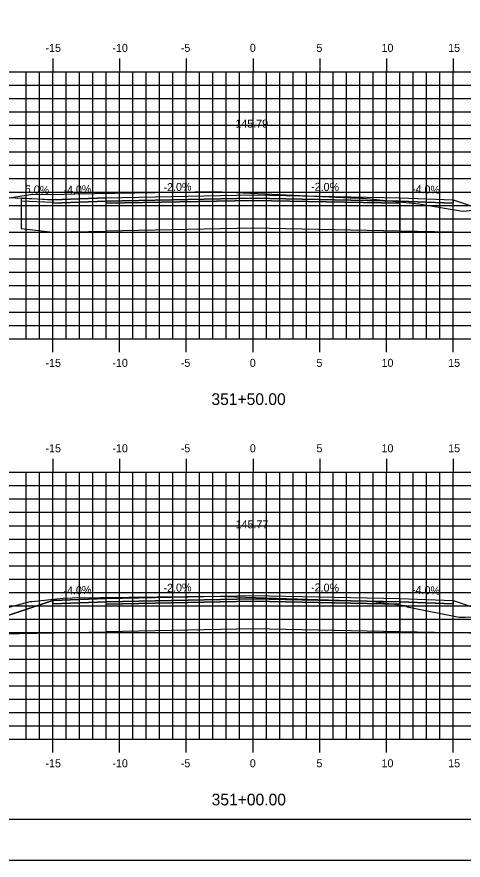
# Model space of a CAD drawing. Extents: x 1144751 to 1144921, y 608981 to 609091.
# Drawn here: x 1144815.9 to 1144849.4, y 608981.3 to 609044.5 of the extents above; entities that cross this region are included whole.
import ezdxf

# ---------------------------------------------------------------- set-up
doc = ezdxf.new("R2010")
doc.units = 0
for name, color, linetype in [('ANNOTATION', 7, 'Continuous'), ('BORDER', 7, 'Continuous'), ('D_Roadway_Centerline', 7, 'Continuous'), ('D_Roadway_Centerline_Text', 7, 'Continuous'), ('D_Roadway_Edge_Shoulder', 7, 'Continuous'), ('D_Roadway_Edge_TW', 7, 'Continuous'), ('D_Roadway_Pavement', 7, 'Continuous'), ('D_Roadway_SlopeLines', 7, 'Continuous'), ('D_Roadway_SubGrade', 7, 'Continuous'), ('H_V ANNOTATION', 7, 'Continuous'), ('MAJOR', 7, 'Continuous'), ('MINOR', 7, 'Continuous'), ('PLOT BOUNDARY', 7, 'Continuous'), ('S_Roadway_Centerline', 7, 'Continuous')]:
    doc.layers.add(name, color=color, linetype=linetype)

msp = doc.modelspace()

# ---------------------------------------------------------------- linework, layer by layer
for points in [[(1144816.245, 609030.888), (1144818.619, 609030.746), (1144822.619, 609030.906), (1144833.619, 609031.126), (1144844.619, 609030.906), (1144848.619, 609030.746), (1144856.342, 609028.171), (1144859.342, 609027.171), (1144862.514, 609028.757), (1144863.764, 609029.299), (1144865.014, 609029.675), (1144866.264, 609029.885), (1144867.514, 609029.928)], [(1144797.455, 609001.234), (1144798.705, 609001.105), (1144799.955, 609000.834), (1144801.205, 609000.422), (1144802.455, 608999.868), (1144807.894, 608997.148), (1144810.894, 608998.148), (1144818.618, 609000.723), (1144818.619, 609000.723), (1144822.619, 609000.883), (1144833.619, 609001.103), (1144844.619, 609000.883), (1144848.619, 609000.723), (1144856.342, 608998.148), (1144859.342, 608997.148), (1144861.625, 608998.29), (1144862.875, 608998.836), (1144864.125, 608999.226), (1144865.375, 608999.458), (1144866.625, 608999.533)]]:
    msp.add_lwpolyline(points)
at = {"layer": 'BORDER'}
msp.add_lwpolyline([(1144758.619, 608984.335), (1144918.619, 608984.335), (1144918.619, 609089.335), (1144758.619, 609089.335)], close=True, dxfattribs=at)
at = {"layer": 'D_Roadway_Edge_Shoulder'}
for points in [[(1144822.619, 609030.906), (1144818.619, 609030.746), (1144818.619, 609030.496), (1144822.619, 609030.656)], [(1144844.619, 609030.906), (1144848.619, 609030.746), (1144848.619, 609030.496), (1144844.619, 609030.656)], [(1144822.619, 609000.883), (1144818.619, 609000.723), (1144818.619, 609000.473), (1144822.619, 609000.633)], [(1144844.619, 609000.883), (1144848.619, 609000.723), (1144848.619, 609000.473), (1144844.619, 609000.633)]]:
    msp.add_lwpolyline(points, close=True, dxfattribs=at)
msp.add_lwpolyline([(1144816.245, 609030.674), (1144818.617, 609030.579), (1144818.619, 609030.746), (1144816.245, 609030.841)], dxfattribs=at)
at = {"layer": 'D_Roadway_Edge_TW'}
for points in [[(1144822.619, 609030.656), (1144822.619, 609030.906), (1144833.619, 609031.126), (1144844.619, 609030.906), (1144844.619, 609030.656), (1144833.619, 609030.876)], [(1144822.619, 609000.633), (1144822.619, 609000.883), (1144833.619, 609001.103), (1144844.619, 609000.883), (1144844.619, 609000.633), (1144833.619, 609000.853)]]:
    msp.add_lwpolyline(points, close=True, dxfattribs=at)
at = {"layer": 'D_Roadway_Pavement'}
for points in [[(1144822.619, 609030.489), (1144822.619, 609030.656), (1144833.619, 609030.876), (1144844.619, 609030.656), (1144844.619, 609030.489), (1144833.619, 609030.709)], [(1144822.619, 609000.466), (1144822.619, 609000.633), (1144833.619, 609000.853), (1144844.619, 609000.633), (1144844.619, 609000.466), (1144833.619, 609000.686)]]:
    msp.add_lwpolyline(points, close=True, dxfattribs=at)
at = {"layer": 'D_Roadway_SlopeLines'}
msp.add_line((1144816.245, 609030.841), (1144798.576, 609031.83), dxfattribs=at)
at = {"layer": 'D_Roadway_SubGrade'}
for points in [[(1144818.619, 609028.326), (1144822.619, 609028.406), (1144822.619, 609030.656), (1144818.619, 609030.496), (1144818.619, 609030.746), (1144816.245, 609030.841), (1144816.245, 609028.6)], [(1144822.619, 609028.406), (1144822.619, 609030.489), (1144833.619, 609030.709), (1144844.619, 609030.489), (1144844.619, 609028.406), (1144833.619, 609028.626)], [(1144844.619, 609030.489), (1144844.619, 609030.656), (1144848.619, 609030.496), (1144848.619, 609030.746), (1144848.619, 609030.746), (1144856.342, 609028.171), (1144844.619, 609028.406)], [(1144822.619, 609000.466), (1144822.619, 609000.633), (1144818.619, 609000.473), (1144818.619, 609000.723), (1144818.618, 609000.723), (1144810.894, 608998.148), (1144822.619, 608998.383)], [(1144822.619, 608998.383), (1144822.619, 609000.466), (1144833.619, 609000.686), (1144844.619, 609000.466), (1144844.619, 608998.383), (1144833.619, 608998.603)], [(1144844.619, 609000.466), (1144844.619, 609000.633), (1144848.619, 609000.473), (1144848.619, 609000.723), (1144848.619, 609000.723), (1144856.342, 608998.148), (1144844.619, 608998.383)]]:
    msp.add_lwpolyline(points, close=True, dxfattribs=at)
at = {"layer": 'MAJOR'}
for p, q in [((1144818.619, 609041.337), (1144818.619, 609040.335)), ((1144823.619, 609041.337), (1144823.619, 609040.335)), ((1144828.619, 609041.337), (1144828.619, 609040.335)), ((1144833.619, 609041.337), (1144833.619, 609040.335)), ((1144838.619, 609041.337), (1144838.619, 609040.335)), ((1144843.619, 609041.337), (1144843.619, 609040.335)), ((1144848.619, 609041.337), (1144848.619, 609040.335)), ((1144763.619, 609040.335), (1144903.619, 609040.335)), ((1144763.619, 609040.335), (1144903.619, 609040.335)), ((1144818.619, 609020.335), (1144818.619, 609040.335)), ((1144823.619, 609020.335), (1144823.619, 609040.335)), ((1144828.619, 609020.335), (1144828.619, 609040.335)), ((1144833.619, 609020.335), (1144833.619, 609040.335)), ((1144838.619, 609020.335), (1144838.619, 609040.335)), ((1144843.619, 609020.335), (1144843.619, 609040.335)), ((1144848.619, 609020.335), (1144848.619, 609040.335)), ((1144763.619, 609035.335), (1144903.619, 609035.335)), ((1144763.619, 609030.335), (1144903.619, 609030.335)), ((1144763.619, 609025.335), (1144903.619, 609025.335)), ((1144763.619, 609020.335), (1144903.619, 609020.335)), ((1144763.619, 609020.335), (1144903.619, 609020.335)), ((1144818.619, 609019.333), (1144818.619, 609020.335)), ((1144823.619, 609019.333), (1144823.619, 609020.335)), ((1144828.619, 609019.333), (1144828.619, 609020.335)), ((1144833.619, 609019.333), (1144833.619, 609020.335)), ((1144838.619, 609019.333), (1144838.619, 609020.335)), ((1144843.619, 609019.333), (1144843.619, 609020.335)), ((1144848.619, 609019.333), (1144848.619, 609020.335)), ((1144818.619, 609011.337), (1144818.619, 609010.335)), ((1144823.619, 609011.337), (1144823.619, 609010.335)), ((1144828.619, 609011.337), (1144828.619, 609010.335)), ((1144833.619, 609011.337), (1144833.619, 609010.335)), ((1144838.619, 609011.337), (1144838.619, 609010.335)), ((1144843.619, 609011.337), (1144843.619, 609010.335)), ((1144848.619, 609011.337), (1144848.619, 609010.335)), ((1144763.619, 609010.335), (1144903.619, 609010.335)), ((1144763.619, 609010.335), (1144903.619, 609010.335)), ((1144818.619, 608990.335), (1144818.619, 609010.335)), ((1144823.619, 608990.335), (1144823.619, 609010.335)), ((1144828.619, 608990.335), (1144828.619, 609010.335)), ((1144833.619, 608990.335), (1144833.619, 609010.335)), ((1144838.619, 608990.335), (1144838.619, 609010.335)), ((1144843.619, 608990.335), (1144843.619, 609010.335)), ((1144848.619, 608990.335), (1144848.619, 609010.335)), ((1144763.619, 609005.335), (1144903.619, 609005.335)), ((1144763.619, 609000.335), (1144903.619, 609000.335)), ((1144763.619, 608995.335), (1144903.619, 608995.335)), ((1144763.619, 608990.335), (1144903.619, 608990.335)), ((1144763.619, 608990.335), (1144903.619, 608990.335)), ((1144818.619, 608989.333), (1144818.619, 608990.335)), ((1144823.619, 608989.333), (1144823.619, 608990.335)), ((1144828.619, 608989.333), (1144828.619, 608990.335)), ((1144833.619, 608989.333), (1144833.619, 608990.335)), ((1144838.619, 608989.333), (1144838.619, 608990.335)), ((1144843.619, 608989.333), (1144843.619, 608990.335)), ((1144848.619, 608989.333), (1144848.619, 608990.335))]:
    msp.add_line(p, q, dxfattribs=at)
at = {"layer": 'MINOR'}
for p, q in [((1144816.619, 609020.335), (1144816.619, 609040.335)), ((1144817.619, 609020.335), (1144817.619, 609040.335)), ((1144819.619, 609020.335), (1144819.619, 609040.335)), ((1144820.619, 609020.335), (1144820.619, 609040.335)), ((1144821.619, 609020.335), (1144821.619, 609040.335)), ((1144822.619, 609020.335), (1144822.619, 609040.335)), ((1144824.619, 609020.335), (1144824.619, 609040.335)), ((1144825.619, 609020.335), (1144825.619, 609040.335)), ((1144826.619, 609020.335), (1144826.619, 609040.335)), ((1144827.619, 609020.335), (1144827.619, 609040.335)), ((1144829.619, 609020.335), (1144829.619, 609040.335)), ((1144830.619, 609020.335), (1144830.619, 609040.335)), ((1144831.619, 609020.335), (1144831.619, 609040.335)), ((1144832.619, 609020.335), (1144832.619, 609040.335)), ((1144834.619, 609020.335), (1144834.619, 609040.335)), ((1144835.619, 609020.335), (1144835.619, 609040.335)), ((1144836.619, 609020.335), (1144836.619, 609040.335)), ((1144837.619, 609020.335), (1144837.619, 609040.335)), ((1144839.619, 609020.335), (1144839.619, 609040.335)), ((1144840.619, 609020.335), (1144840.619, 609040.335)), ((1144841.619, 609020.335), (1144841.619, 609040.335)), ((1144842.619, 609020.335), (1144842.619, 609040.335)), ((1144844.619, 609020.335), (1144844.619, 609040.335)), ((1144845.619, 609020.335), (1144845.619, 609040.335)), ((1144846.619, 609020.335), (1144846.619, 609040.335)), ((1144847.619, 609020.335), (1144847.619, 609040.335)), ((1144763.619, 609039.335), (1144903.619, 609039.335)), ((1144763.619, 609038.335), (1144903.619, 609038.335)), ((1144763.619, 609037.335), (1144903.619, 609037.335)), ((1144763.619, 609036.335), (1144903.619, 609036.335)), ((1144763.619, 609034.335), (1144903.619, 609034.335)), ((1144763.619, 609033.335), (1144903.619, 609033.335)), ((1144763.619, 609032.335), (1144903.619, 609032.335)), ((1144763.619, 609031.335), (1144903.619, 609031.335)), ((1144763.619, 609029.335), (1144903.619, 609029.335)), ((1144763.619, 609028.335), (1144903.619, 609028.335)), ((1144763.619, 609027.335), (1144903.619, 609027.335)), ((1144763.619, 609026.335), (1144903.619, 609026.335)), ((1144763.619, 609024.335), (1144903.619, 609024.335)), ((1144763.619, 609023.335), (1144903.619, 609023.335)), ((1144763.619, 609022.335), (1144903.619, 609022.335)), ((1144763.619, 609021.335), (1144903.619, 609021.335)), ((1144816.619, 608990.335), (1144816.619, 609010.335)), ((1144817.619, 608990.335), (1144817.619, 609010.335)), ((1144819.619, 608990.335), (1144819.619, 609010.335)), ((1144820.619, 608990.335), (1144820.619, 609010.335)), ((1144821.619, 608990.335), (1144821.619, 609010.335)), ((1144822.619, 608990.335), (1144822.619, 609010.335)), ((1144824.619, 608990.335), (1144824.619, 609010.335)), ((1144825.619, 608990.335), (1144825.619, 609010.335)), ((1144826.619, 608990.335), (1144826.619, 609010.335)), ((1144827.619, 608990.335), (1144827.619, 609010.335)), ((1144829.619, 608990.335), (1144829.619, 609010.335)), ((1144830.619, 608990.335), (1144830.619, 609010.335)), ((1144831.619, 608990.335), (1144831.619, 609010.335)), ((1144832.619, 608990.335), (1144832.619, 609010.335)), ((1144834.619, 608990.335), (1144834.619, 609010.335)), ((1144835.619, 608990.335), (1144835.619, 609010.335)), ((1144836.619, 608990.335), (1144836.619, 609010.335)), ((1144837.619, 608990.335), (1144837.619, 609010.335)), ((1144839.619, 608990.335), (1144839.619, 609010.335)), ((1144840.619, 608990.335), (1144840.619, 609010.335)), ((1144841.619, 608990.335), (1144841.619, 609010.335)), ((1144842.619, 608990.335), (1144842.619, 609010.335)), ((1144844.619, 608990.335), (1144844.619, 609010.335)), ((1144845.619, 608990.335), (1144845.619, 609010.335)), ((1144846.619, 608990.335), (1144846.619, 609010.335)), ((1144847.619, 608990.335), (1144847.619, 609010.335)), ((1144763.619, 609009.335), (1144903.619, 609009.335)), ((1144763.619, 609008.335), (1144903.619, 609008.335)), ((1144763.619, 609007.335), (1144903.619, 609007.335)), ((1144763.619, 609006.335), (1144903.619, 609006.335)), ((1144763.619, 609004.335), (1144903.619, 609004.335)), ((1144763.619, 609003.335), (1144903.619, 609003.335)), ((1144763.619, 609002.335), (1144903.619, 609002.335)), ((1144763.619, 609001.335), (1144903.619, 609001.335)), ((1144763.619, 608999.335), (1144903.619, 608999.335)), ((1144763.619, 608998.335), (1144903.619, 608998.335)), ((1144763.619, 608997.335), (1144903.619, 608997.335)), ((1144763.619, 608996.335), (1144903.619, 608996.335)), ((1144763.619, 608994.335), (1144903.619, 608994.335)), ((1144763.619, 608993.335), (1144903.619, 608993.335)), ((1144763.619, 608992.335), (1144903.619, 608992.335)), ((1144763.619, 608991.335), (1144903.619, 608991.335))]:
    msp.add_line(p, q, dxfattribs=at)
at = {"layer": 'PLOT BOUNDARY'}
msp.add_lwpolyline([(1144750.526, 608981.276), (1144920.526, 608981.276), (1144920.526, 609091.276), (1144750.526, 609091.276)], close=True, dxfattribs=at)
at = {"layer": 'S_Roadway_Centerline'}
for points in [[(1144783.338, 609031.937), (1144785.588, 609032.156), (1144803.411, 609031.709), (1144806.171, 609031.584), (1144812.1, 609030.451), (1144812.366, 609030.413), (1144812.487, 609030.445), (1144817.107, 609031.177), (1144819.29, 609031.161), (1144819.463, 609031.18), (1144820.262, 609031.19), (1144830.751, 609031.377), (1144840.894, 609030.911), (1144841.691, 609030.885), (1144841.859, 609030.863), (1144846.068, 609030.451), (1144846.347, 609030.396), (1144849.307, 609029.907), (1144849.614, 609029.914), (1144853.774, 609030.361), (1144875.416, 609029.679), (1144877.702, 609029.675)], [(1144784.091, 609001.855), (1144804.815, 609000.892), (1144806.118, 609000.876), (1144806.664, 609000.752), (1144813.58, 608999.76), (1144813.762, 608999.807), (1144816.936, 609000.648), (1144817.059, 609000.66), (1144819.398, 609000.91), (1144820.085, 609000.917), (1144830.699, 609001.046), (1144841.624, 609000.698), (1144842.406, 609000.678), (1144842.648, 609000.652), (1144844.954, 609000.353), (1144845.157, 609000.264), (1144849.049, 608999.486), (1144849.52, 608999.482), (1144853.374, 608999.568), (1144879.018, 608999.501), (1144882.968, 608999.398)]]:
    msp.add_lwpolyline(points, dxfattribs=at)

# ---------------------------------------------------------------- texts
at = {"layer": 'ANNOTATION'}
for s, rotation, p in [('6.0%', 356.56637, (1144816.509, 609031.274)), ('-4.0%', 2.29061, (1144819.435, 609031.179)), ('-2.0%', 1.14576, (1144826.922, 609031.392)), ('-2.0%', 358.85424, (1144837.962, 609031.439)), ('-4.0%', 357.70939, (1144845.515, 609031.271)), ('-2.0%', 1.14576, (1144826.922, 609001.369)), ('-2.0%', 358.85424, (1144837.962, 609001.416)), ('-4.0%', 2.29061, (1144819.435, 609001.156)), ('-4.0%', 357.70939, (1144845.515, 609001.248))]:
    msp.add_text(s, height=0.6, rotation=rotation, dxfattribs=at).set_placement(p)
at = {"layer": 'D_Roadway_Centerline'}
for s, p in [('C', (1144833.614, 609031.126)), ('L', (1144833.619, 609031.119)), ('C', (1144833.614, 609001.103)), ('L', (1144833.619, 609001.095))]:
    msp.add_text(s, height=0.0146, dxfattribs=at).set_placement(p)
at = {"layer": 'D_Roadway_Centerline_Text'}
for s, p in [('145.79', (1144832.297, 609036.158)), ('145.77', (1144832.313, 609006.135))]:
    msp.add_text(s, height=0.6, dxfattribs=at).set_placement(p)
at = {"layer": 'H_V ANNOTATION'}
for s, height, p in [('-15', 0.6, (1144818.076, 609041.835)), ('-10', 0.6, (1144823.084, 609041.835)), ('-5', 0.6, (1144828.209, 609041.835)), ('0', 0.6, (1144833.378, 609041.835)), ('5', 0.6, (1144838.37, 609041.835)), ('10', 0.6, (1144843.244, 609041.835)), ('15', 0.6, (1144848.236, 609041.835)), ('-15', 0.6, (1144818.076, 609018.235)), ('-10', 0.6, (1144823.084, 609018.235)), ('-5', 0.6, (1144828.209, 609018.235)), ('0', 0.6, (1144833.378, 609018.235)), ('5', 0.6, (1144838.37, 609018.235)), ('10', 0.6, (1144843.244, 609018.235)), ('15', 0.6, (1144848.236, 609018.235)), ('351+50.00', 0.875, (1144830.505, 609015.378)), ('-15', 0.6, (1144818.076, 609011.835)), ('-10', 0.6, (1144823.084, 609011.835)), ('-5', 0.6, (1144828.209, 609011.835)), ('0', 0.6, (1144833.378, 609011.835)), ('5', 0.6, (1144838.37, 609011.835)), ('10', 0.6, (1144843.244, 609011.835)), ('15', 0.6, (1144848.236, 609011.835)), ('-15', 0.6, (1144818.076, 608988.235)), ('-10', 0.6, (1144823.084, 608988.235)), ('-5', 0.6, (1144828.209, 608988.235)), ('0', 0.6, (1144833.378, 608988.235)), ('5', 0.6, (1144838.37, 608988.235)), ('10', 0.6, (1144843.244, 608988.235)), ('15', 0.6, (1144848.236, 608988.235)), ('351+00.00', 0.875, (1144830.521, 608985.378))]:
    msp.add_text(s, height=height, dxfattribs=at).set_placement(p)
at = {"layer": 'S_Roadway_Centerline'}
for s, p in [('L', (1144830.742, 609031.37)), ('C', (1144830.745, 609031.377)), ('L', (1144830.691, 609001.039)), ('C', (1144830.694, 609001.046))]:
    msp.add_text(s, height=0.0146, dxfattribs=at).set_placement(p)

doc.saveas('drawing.dxf')
